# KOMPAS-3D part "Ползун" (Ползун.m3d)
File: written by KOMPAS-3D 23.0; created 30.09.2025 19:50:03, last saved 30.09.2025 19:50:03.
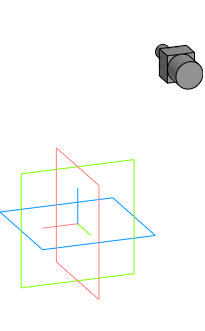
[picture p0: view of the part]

Document properties: Автор: Inspektor_Kot; Полное имя файла: I:\Autodesk Inventor Projects\ИМ-ИТ ЦД\Вариант 6\Ползун.m3d

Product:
- Part/product: Ползун

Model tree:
1. Эскиз:1  (with: Элемент выдавливания:1)  (labels: I:\Autodesk Inventor Projects\ИМ-ИТ ЦД\Вариант 6\Шатун.a3d)
2. Элемент выдавливания:1
     Расстояние 2 = 22
3. Эскиз:2  (with: Элемент выдавливания:1, Элемент выдавливания:2)  (labels: I:\Autodesk Inventor Projects\ИМ-ИТ ЦД\Вариант 6\Шатун.a3d)
4. Элемент выдавливания:2
     Расстояние 1 = 10; Расстояние 2 = 9.5
5. Эскиз:3  (with: Элемент выдавливания:2)
6. Элемент выдавливания:3
     Расстояние 2 = 10
7. Скругление:1  (with: Элемент выдавливания:2)
     Радиус = 3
